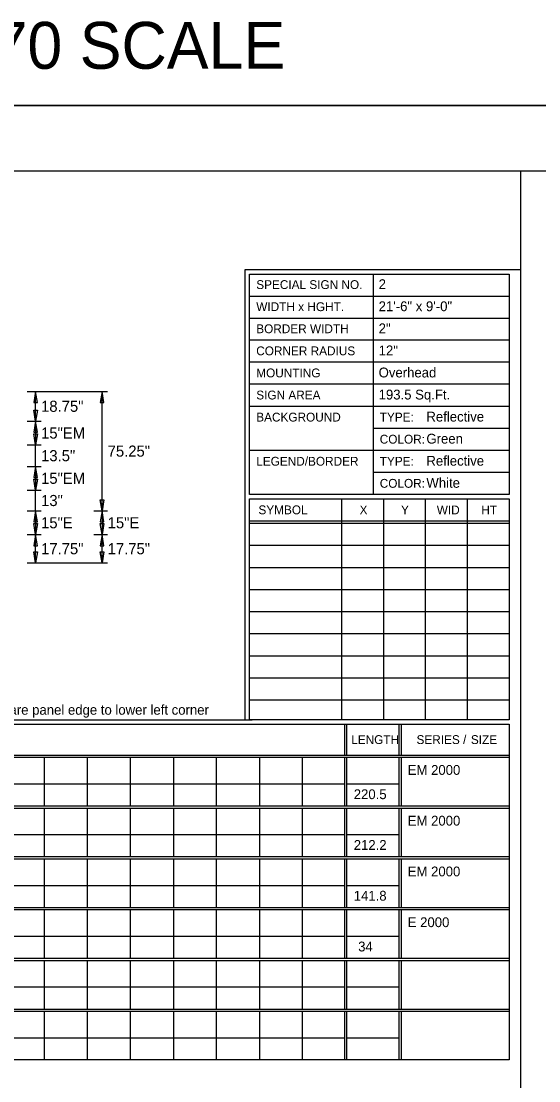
# Model space of a CAD drawing. Extents: x 2149961 to 2150220, y 145114 to 145240.
# Drawn here: x 2150109.2 to 2150136.4, y 145168.7 to 145224.4 of the extents above; entities that cross this region are included whole.
import ezdxf

# ---------------------------------------------------------------- set-up
doc = ezdxf.new("R2010")
doc.units = 0
for name, color, linetype in [('BORDER', 7, 'Continuous'), ('GSDIMS', 7, 'Continuous'), ('GSSHT', 7, 'Continuous'), ('Level 1', 7, 'Continuous'), ('PDF', 7, 'Continuous'), ('TEXT', 7, 'Continuous')]:
    doc.layers.add(name, color=color, linetype=linetype)

msp = doc.modelspace()

# ---------------------------------------------------------------- linework, layer by layer
at = {"layer": 'BORDER'}
for p, q in [((2150010.458, 145219.948), (2150174.061, 145219.948)), ((2150171.536, 145216.512), (2150017.557, 145216.512))]:
    msp.add_line(p, q, dxfattribs=at)
at = {"layer": 'GSDIMS'}
for p, q in [((2150109.508, 145204.945), (2150110.237, 145204.945)), ((2150109.508, 145204.945), (2150113.008, 145204.945)), ((2150109.945, 145203.382), (2150109.945, 145204.945)), ((2150113.008, 145204.945), (2150113.737, 145204.945)), ((2150113.445, 145198.674), (2150113.445, 145204.945)), ((2150109.508, 145203.382), (2150110.237, 145203.382)), ((2150109.508, 145203.382), (2150110.237, 145203.382)), ((2150109.945, 145203.382), (2150109.945, 145202.132)), ((2150109.508, 145202.132), (2150110.237, 145202.132)), ((2150109.508, 145202.132), (2150110.237, 145202.132)), ((2150109.945, 145201.007), (2150109.945, 145202.132)), ((2150109.508, 145201.007), (2150110.237, 145201.007)), ((2150109.508, 145201.007), (2150110.237, 145201.007)), ((2150109.945, 145201.007), (2150109.945, 145199.757)), ((2150109.508, 145199.757), (2150110.237, 145199.757)), ((2150109.508, 145199.757), (2150110.237, 145199.757)), ((2150109.945, 145198.674), (2150109.945, 145199.757)), ((2150109.508, 145198.674), (2150110.237, 145198.674)), ((2150109.508, 145198.674), (2150110.237, 145198.674)), ((2150109.945, 145198.674), (2150109.945, 145197.424)), ((2150113.008, 145198.674), (2150113.737, 145198.674)), ((2150113.008, 145198.674), (2150113.737, 145198.674)), ((2150113.445, 145198.674), (2150113.445, 145197.424)), ((2150109.508, 145197.424), (2150110.237, 145197.424)), ((2150109.508, 145197.424), (2150110.237, 145197.424)), ((2150109.945, 145195.945), (2150109.945, 145197.424)), ((2150113.008, 145197.424), (2150113.737, 145197.424)), ((2150113.008, 145197.424), (2150113.737, 145197.424)), ((2150113.445, 145195.945), (2150113.445, 145197.424)), ((2150109.508, 145195.945), (2150110.237, 145195.945)), ((2150109.508, 145195.945), (2150113.008, 145195.945)), ((2150113.008, 145195.945), (2150113.737, 145195.945))]:
    msp.add_line(p, q, dxfattribs=at)
for points in [[(2150109.945, 145204.945), (2150109.848, 145204.361), (2150110.043, 145204.361)], [(2150113.445, 145204.945), (2150113.348, 145204.361), (2150113.543, 145204.361)], [(2150109.945, 145203.382), (2150109.848, 145203.966), (2150110.043, 145203.966)], [(2150109.945, 145203.382), (2150109.848, 145202.799), (2150110.043, 145202.799)], [(2150109.945, 145202.132), (2150109.848, 145202.716), (2150110.043, 145202.716)], [(2150109.945, 145201.007), (2150109.848, 145200.424), (2150110.043, 145200.424)], [(2150109.945, 145199.757), (2150109.848, 145200.341), (2150110.043, 145200.341)], [(2150113.445, 145198.674), (2150113.348, 145199.257), (2150113.543, 145199.257)], [(2150109.945, 145198.674), (2150109.848, 145198.091), (2150110.043, 145198.091)], [(2150113.445, 145198.674), (2150113.348, 145198.091), (2150113.543, 145198.091)], [(2150109.945, 145197.424), (2150109.848, 145198.007), (2150110.043, 145198.007)], [(2150113.445, 145197.424), (2150113.348, 145198.007), (2150113.543, 145198.007)], [(2150109.945, 145197.424), (2150109.848, 145196.841), (2150110.043, 145196.841)], [(2150113.445, 145197.424), (2150113.348, 145196.841), (2150113.543, 145196.841)], [(2150109.945, 145195.945), (2150109.848, 145196.528), (2150110.043, 145196.528)], [(2150113.445, 145195.945), (2150113.348, 145196.528), (2150113.543, 145196.528)]]:
    msp.add_lwpolyline(points, close=True, dxfattribs=at)
at = {"layer": 'Level 1'}
for p, q in [((2150135.447, 145216.512), (2150135.447, 145124.606)), ((2150120.969, 145211.34), (2150135.447, 145211.34)), ((2150127.694, 145211.108), (2150127.694, 145199.537)), ((2150121.201, 145209.949), (2150134.843, 145209.949)), ((2150121.201, 145208.789), (2150134.843, 145208.789)), ((2150121.201, 145207.653), (2150134.843, 145207.653)), ((2150121.201, 145206.494), (2150134.843, 145206.494)), ((2150121.201, 145205.334), (2150134.843, 145205.334)), ((2150121.201, 145204.175), (2150134.843, 145204.175)), ((2150127.694, 145203.015), (2150134.843, 145203.015)), ((2150121.201, 145201.856), (2150134.843, 145201.856)), ((2150127.694, 145200.696), (2150134.843, 145200.696)), ((2150121.201, 145187.705), (2150121.201, 145199.305)), ((2150121.201, 145199.305), (2150134.843, 145199.305)), ((2150126.031, 145199.299), (2150126.031, 145198.14)), ((2150128.234, 145199.299), (2150128.234, 145198.14)), ((2150130.437, 145199.299), (2150130.437, 145198.14)), ((2150132.64, 145199.299), (2150132.64, 145198.14)), ((2150134.843, 145199.305), (2150134.843, 145187.705)), ((2150121.201, 145198.14), (2150134.843, 145198.14)), ((2150121.201, 145198.024), (2150134.843, 145198.024)), ((2150126.031, 145198.14), (2150126.031, 145187.705)), ((2150128.234, 145198.14), (2150128.234, 145187.705)), ((2150130.437, 145198.14), (2150130.437, 145187.705)), ((2150132.64, 145198.14), (2150132.64, 145187.705)), ((2150121.201, 145196.864), (2150134.843, 145196.864)), ((2150121.201, 145195.705), (2150134.843, 145195.705)), ((2150121.201, 145194.545), (2150134.843, 145194.545)), ((2150121.201, 145193.386), (2150134.843, 145193.386)), ((2150121.201, 145192.227), (2150134.843, 145192.227)), ((2150121.201, 145191.067), (2150134.843, 145191.067)), ((2150121.201, 145189.908), (2150134.843, 145189.908)), ((2150121.201, 145188.748), (2150134.843, 145188.748)), ((2150076.316, 145187.705), (2150121.342, 145187.705)), ((2150134.843, 145187.705), (2150121.201, 145187.705)), ((2150126.185, 145187.473), (2150126.185, 145185.849)), ((2150126.301, 145187.473), (2150126.301, 145185.849)), ((2150129.048, 145187.473), (2150129.048, 145185.849)), ((2150129.164, 145187.473), (2150129.164, 145185.849)), ((2150076.548, 145185.849), (2150134.843, 145185.849)), ((2150076.548, 145185.733), (2150134.843, 145185.733)), ((2150110.405, 145185.733), (2150110.405, 145183.183)), ((2150112.654, 145185.733), (2150112.654, 145183.183)), ((2150114.927, 145185.733), (2150114.927, 145183.183)), ((2150117.199, 145185.733), (2150117.199, 145183.183)), ((2150119.449, 145185.733), (2150119.449, 145183.183)), ((2150121.721, 145185.733), (2150121.721, 145183.183)), ((2150123.97, 145185.733), (2150123.97, 145183.183)), ((2150126.185, 145185.733), (2150126.185, 145183.183)), ((2150126.301, 145185.733), (2150126.301, 145183.183)), ((2150129.048, 145185.733), (2150129.048, 145183.183)), ((2150129.164, 145185.733), (2150129.164, 145183.183)), ((2150076.548, 145184.342), (2150126.185, 145184.342)), ((2150126.301, 145184.342), (2150129.048, 145184.342)), ((2150076.548, 145183.183), (2150134.843, 145183.183)), ((2150076.548, 145183.067), (2150134.843, 145183.067)), ((2150110.405, 145183.067), (2150110.405, 145180.516)), ((2150112.654, 145183.067), (2150112.654, 145180.516)), ((2150114.927, 145183.067), (2150114.927, 145180.516)), ((2150117.199, 145183.067), (2150117.199, 145180.516)), ((2150119.449, 145183.067), (2150119.449, 145180.516)), ((2150121.721, 145183.067), (2150121.721, 145180.516)), ((2150123.97, 145183.067), (2150123.97, 145180.516)), ((2150126.185, 145183.067), (2150126.185, 145180.516)), ((2150126.301, 145183.067), (2150126.301, 145180.516)), ((2150129.048, 145183.067), (2150129.048, 145180.516)), ((2150129.164, 145183.067), (2150129.164, 145180.516)), ((2150076.548, 145181.675), (2150126.185, 145181.675)), ((2150126.301, 145181.675), (2150129.048, 145181.675)), ((2150076.548, 145180.516), (2150134.843, 145180.516)), ((2150076.548, 145180.4), (2150134.843, 145180.4)), ((2150110.405, 145180.4), (2150110.405, 145177.849)), ((2150112.654, 145180.4), (2150112.654, 145177.849)), ((2150114.927, 145180.4), (2150114.927, 145177.849)), ((2150117.199, 145180.4), (2150117.199, 145177.849)), ((2150119.449, 145180.4), (2150119.449, 145177.849)), ((2150121.721, 145180.4), (2150121.721, 145177.849)), ((2150123.97, 145180.4), (2150123.97, 145177.849)), ((2150126.185, 145180.4), (2150126.185, 145177.849)), ((2150126.301, 145180.4), (2150126.301, 145177.849)), ((2150129.048, 145180.4), (2150129.048, 145177.849)), ((2150129.164, 145180.4), (2150129.164, 145177.849)), ((2150076.548, 145179.008), (2150126.185, 145179.008)), ((2150126.301, 145179.008), (2150129.048, 145179.008)), ((2150076.548, 145177.849), (2150134.843, 145177.849)), ((2150076.548, 145177.733), (2150134.843, 145177.733)), ((2150110.405, 145177.733), (2150110.405, 145175.182)), ((2150112.654, 145177.733), (2150112.654, 145175.182)), ((2150114.927, 145177.733), (2150114.927, 145175.182)), ((2150117.199, 145177.733), (2150117.199, 145175.182)), ((2150119.449, 145177.733), (2150119.449, 145175.182)), ((2150121.721, 145177.733), (2150121.721, 145175.182)), ((2150123.97, 145177.733), (2150123.97, 145175.182)), ((2150126.185, 145177.733), (2150126.185, 145175.182)), ((2150126.301, 145177.733), (2150126.301, 145175.182)), ((2150129.048, 145177.733), (2150129.048, 145175.182)), ((2150129.164, 145177.733), (2150129.164, 145175.182)), ((2150076.548, 145176.342), (2150126.185, 145176.342)), ((2150126.301, 145176.342), (2150129.048, 145176.342)), ((2150076.548, 145175.182), (2150134.843, 145175.182)), ((2150076.548, 145175.066), (2150134.843, 145175.066)), ((2150110.405, 145175.066), (2150110.405, 145172.515)), ((2150112.654, 145175.066), (2150112.654, 145172.515)), ((2150114.927, 145175.066), (2150114.927, 145172.515)), ((2150117.199, 145175.066), (2150117.199, 145172.515)), ((2150119.449, 145175.066), (2150119.449, 145172.515)), ((2150121.721, 145175.066), (2150121.721, 145172.515)), ((2150123.97, 145175.066), (2150123.97, 145172.515)), ((2150126.185, 145175.066), (2150126.185, 145172.515)), ((2150126.301, 145175.066), (2150126.301, 145172.515)), ((2150129.048, 145175.066), (2150129.048, 145172.515)), ((2150129.164, 145175.066), (2150129.164, 145172.515)), ((2150076.548, 145173.675), (2150126.185, 145173.675)), ((2150126.301, 145173.675), (2150129.048, 145173.675)), ((2150076.548, 145172.515), (2150134.843, 145172.515)), ((2150076.548, 145172.399), (2150134.843, 145172.399)), ((2150110.405, 145172.399), (2150110.405, 145169.849)), ((2150112.654, 145172.399), (2150112.654, 145169.849)), ((2150114.927, 145172.399), (2150114.927, 145169.849)), ((2150117.199, 145172.399), (2150117.199, 145169.849)), ((2150119.449, 145172.399), (2150119.449, 145169.849)), ((2150121.721, 145172.399), (2150121.721, 145169.849)), ((2150123.97, 145172.399), (2150123.97, 145169.849)), ((2150126.185, 145172.399), (2150126.185, 145169.849)), ((2150126.301, 145172.399), (2150126.301, 145169.849)), ((2150129.048, 145172.399), (2150129.048, 145169.849)), ((2150129.164, 145172.399), (2150129.164, 145169.849)), ((2150076.548, 145171.008), (2150126.185, 145171.008)), ((2150126.301, 145171.008), (2150129.048, 145171.008))]:
    msp.add_line(p, q, dxfattribs=at)
msp.add_lwpolyline([(2150120.969, 145187.705), (2150120.969, 145211.34)], dxfattribs=at)
for points in [[(2150121.201, 145211.108), (2150134.843, 145211.108), (2150134.843, 145199.537), (2150121.201, 145199.537)], [(2150076.548, 145187.473), (2150134.843, 145187.473), (2150134.843, 145169.849), (2150076.548, 145169.849)]]:
    msp.add_lwpolyline(points, close=True, dxfattribs=at)
at = {"layer": 'PDF'}
msp.add_lwpolyline([(2150010.458, 145114.088), (2150174.061, 145114.088), (2150174.061, 145219.948), (2150010.458, 145219.948)], close=True, dxfattribs=at)

# ---------------------------------------------------------------- texts
at = {"layer": 'GSDIMS'}
for s, p in [('18.75"', (2150110.237, 145203.872)), ('15"EM', (2150110.237, 145202.466)), ('13.5"', (2150110.237, 145201.278)), ('75.25"', (2150113.737, 145201.518)), ('15"EM', (2150110.237, 145200.091)), ('13"', (2150110.237, 145198.924)), ('15"E', (2150110.237, 145197.757)), ('15"E', (2150113.737, 145197.757)), ('17.75"', (2150110.237, 145196.393)), ('17.75"', (2150113.737, 145196.393))]:
    msp.add_text(s, height=0.5833, dxfattribs=at).set_placement(p)
at = {"layer": 'GSSHT'}
for s, height, p in [('2', 0.517, (2150127.983, 145210.315)), ('Overhead', 0.5165, (2150127.983, 145205.679))]:
    msp.add_text(s, height=height, dxfattribs=at).set_placement(p)
at = {"layer": 'Level 1'}
for s, height, p in [('SPECIAL SIGN NO.', 0.46374, (2150121.549, 145210.32)), ('WIDTH x HGHT.', 0.46374, (2150121.549, 145209.16)), ('21\'-6" x 9\'-0"', 0.51652, (2150127.983, 145209.156)), ('BORDER WIDTH', 0.46374, (2150121.549, 145208.001)), ('2"', 0.5165, (2150127.983, 145207.997)), ('CORNER RADIUS', 0.46374, (2150121.549, 145206.841)), ('12"', 0.5165, (2150127.983, 145206.838)), ('MOUNTING', 0.4637, (2150121.549, 145205.682)), ('193.5 Sq.Ft.', 0.51652, (2150127.983, 145204.52)), ('SIGN AREA', 0.4638, (2150121.549, 145204.522)), ('BACKGROUND', 0.4637, (2150121.549, 145203.363)), ('TYPE:', 0.4637, (2150128.042, 145203.363)), ('Reflective', 0.5165, (2150130.494, 145203.361)), ('COLOR:', 0.4637, (2150128.042, 145202.203)), ('Green', 0.5165, (2150130.494, 145202.203)), ('LEGEND/BORDER', 0.46374, (2150121.549, 145201.044)), ('TYPE:', 0.4637, (2150128.042, 145201.044)), ('Reflective', 0.5165, (2150130.494, 145201.044)), ('COLOR:', 0.4637, (2150128.042, 145199.885)), ('White', 0.5165, (2150130.494, 145199.885)), ('SYMBOL', 0.4637, (2150121.665, 145198.493)), ('X', 0.464, (2150126.981, 145198.488)), ('Y', 0.464, (2150129.161, 145198.488)), ('WID', 0.4637, (2150131.04, 145198.488)), ('HT', 0.4637, (2150133.382, 145198.488)), ('Letter locations are panel edge to lower left corner', 0.51652, (2150103.701, 145187.968)), ('LENGTH', 0.4638, (2150126.541, 145186.429)), ('LENGTH', 0.4638, (2150126.541, 145186.429)), ('SERIES /', 0.4638, (2150129.975, 145186.429)), ('SIZE', 0.4638, (2150132.832, 145186.429)), ('EM 2000', 0.5165, (2150129.512, 145184.81)), ('220.5', 0.5165, (2150126.674, 145183.535)), ('EM 2000', 0.5165, (2150129.512, 145182.145)), ('212.2', 0.5165, (2150126.674, 145180.87)), ('EM 2000', 0.5165, (2150129.512, 145179.479)), ('141.8', 0.5165, (2150126.674, 145178.204)), ('E 2000', 0.5165, (2150129.512, 145176.814)), ('34', 0.5165, (2150126.907, 145175.539))]:
    msp.add_text(s, height=height, dxfattribs=at).set_placement(p)
at = {"layer": 'TEXT'}
msp.add_text('BORDER AND REPORT 70 SCALE', height=2.46401, dxfattribs=at).set_placement((2150070.157, 145221.883))

doc.saveas('drawing.dxf')
